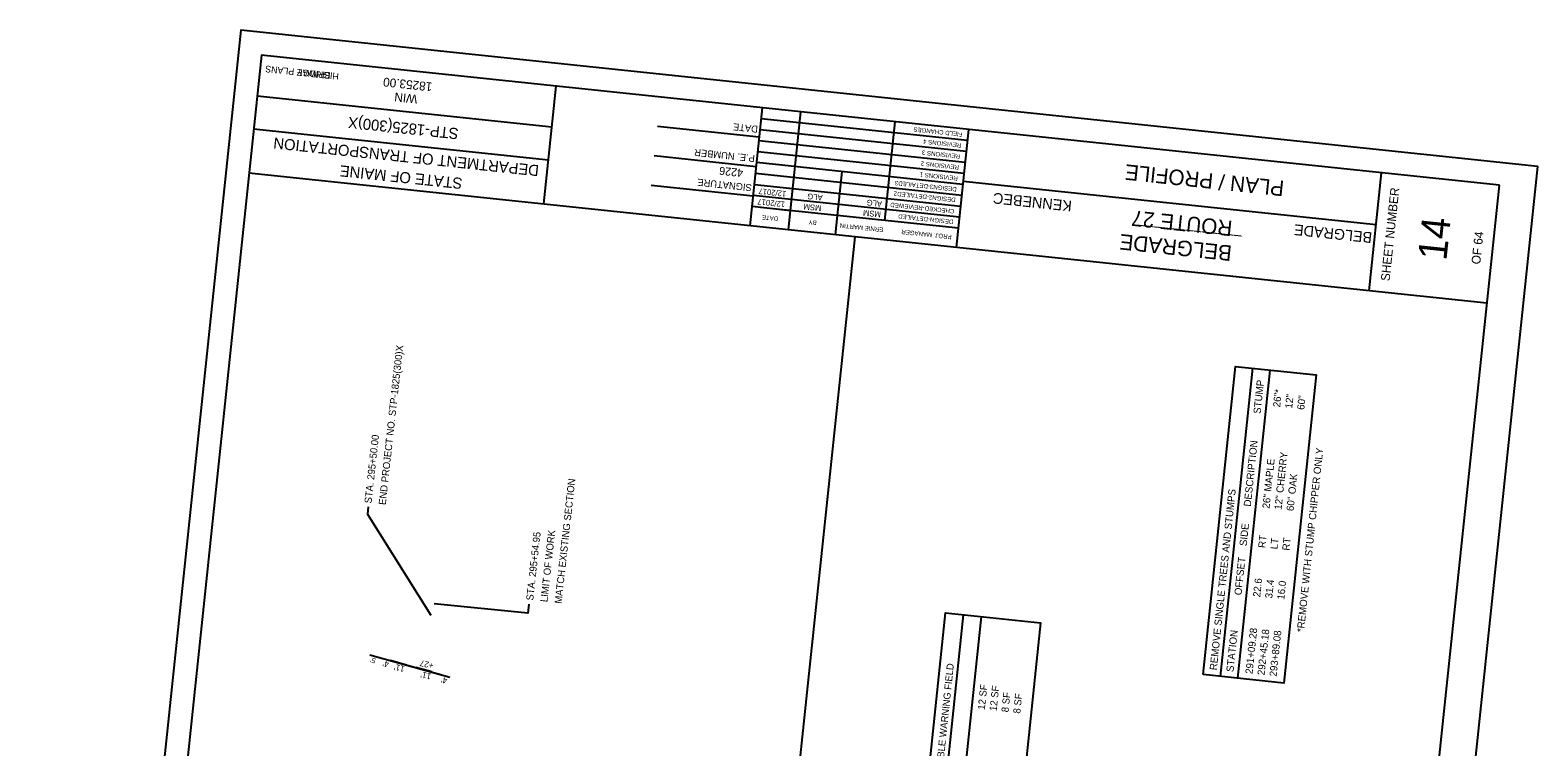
# Model space of a CAD drawing. Extents: x 1111051 to 1111686, y 618367 to 619270.
# Drawn here: x 1111051 to 1111686, y 618968 to 619270 of the extents above; entities that cross this region are included whole.
import ezdxf

# ---------------------------------------------------------------- set-up
doc = ezdxf.new("R2010")
doc.units = 0
for name, color, linetype in [('H_V ANNOTATION', 7, 'Continuous'), ('MINOR', 7, 'Continuous'), ('S_Roadway_Centerline', 7, 'Continuous'), ('S_Roadway_Sidewalks_Paved', 7, 'Continuous'), ('S_Utilities_GuyWire3', 7, 'Continuous')]:
    doc.layers.add(name, color=color, linetype=linetype)

msp = doc.modelspace()

# ---------------------------------------------------------------- linework, layer by layer
at = {"layer": 'MINOR'}
for p, q in [((1111148.14, 619259.69), (1111064.52, 618464.07)), ((1111670.25, 619204.81), (1111148.13, 619259.69)), ((1111267.26, 619196.9), (1111272.48, 619246.62)), ((1111270.65, 619229.34), (1111146.34, 619242.4)), ((1111354.23, 619187.75), (1111359.46, 619237.48)), ((1111269.19, 619215.44), (1111144.88, 619228.5)), ((1111358.15, 619225.05), (1111315.15, 619229.57)), ((1111441.25, 619178.61), (1111446.48, 619228.33)), ((1111356.85, 619212.62), (1111313.85, 619217.14)), ((1111665.02, 619155.09), (1111142.9, 619209.96)), ((1111615.3, 619160.31), (1111620.52, 619210.04)), ((1111355.54, 619200.18), (1111312.54, 619204.7)), ((1111618.22, 619188.12), (1111444.18, 619206.41)), ((1111586.64, 618409.2), (1111670.26, 619204.81)), ((1111320.11, 618437.21), (1111398.5, 619183.1))]:
    msp.add_line(p, q, dxfattribs=at)
for points in [[(1111370.4, 619186.05), (1111375.62, 619235.78)], [(1111445.49, 619219.07), (1111358.49, 619228.22)], [(1111445.98, 619223.71), (1111358.97, 619232.85)], [(1111411.02, 619189.9), (1111415.4, 619231.6)], [(1111445.01, 619214.44), (1111358, 619223.58)], [(1111444.03, 619205.17), (1111357.03, 619214.32)], [(1111444.52, 619209.81), (1111357.51, 619218.95)], [(1111443.55, 619200.54), (1111356.54, 619209.69)], [(1111391.13, 619191.99), (1111393.08, 619210.53)], [(1111356.05, 619205.05), (1111443.06, 619195.91)], [(1111371.24, 619194.08), (1111355.08, 619195.78)], [(1111442.57, 619191.28), (1111355.57, 619200.42)], [(1111442.08, 619186.64), (1111358.59, 619195.42)], [(1111390.29, 619183.96), (1111391.13, 619192)]]:
    msp.add_lwpolyline(points, dxfattribs=at)
at = {"layer": 'S_Roadway_Sidewalks_Paved'}
msp.add_lwpolyline([(1111597.62, 618367.35), (1111686.47, 619212.69), (1111139.49, 619270.18), (1111050.64, 618424.84)], close=True, dxfattribs=at)
at = {"layer": 'S_Utilities_GuyWire3'}
for p, q in [((1111552.66, 618997.7), (1111566.31, 619127.65)), ((1111559.96, 618996.93), (1111573.62, 619126.88)), ((1111433.07, 618917.25), (1111444.25, 619023.7)), ((1111440.6, 618916.46), (1111451.79, 619022.91)), ((1111193.94, 619006.77), (1111227.68, 618997.45)), ((1111209.36, 619002.51), (1111202.62, 619004.37)), ((1111206.47, 619003.31), (1111213.22, 619001.44)), ((1111219.97, 618999.58), (1111213.22, 619001.44)), ((1111217.07, 619000.38), (1111223.82, 618998.51))]:
    msp.add_line(p, q, dxfattribs=at)
for points in [[(1111545.35, 618998.46), (1111559.01, 619128.42), (1111592.98, 619124.85), (1111579.32, 618994.89)], [(1111425.53, 618918.04), (1111436.72, 619024.49), (1111476.79, 619020.28), (1111465.6, 618913.83)]]:
    msp.add_lwpolyline(points, close=True, dxfattribs=at)
for points in [[(1111193.19, 619069.27), (1111192.86, 619066.07), (1111219.58, 619023.54)], [(1111260.99, 619028.14), (1111260.49, 619024.35), (1111220.97, 619028.29)]]:
    msp.add_lwpolyline(points, dxfattribs=at)

# ---------------------------------------------------------------- texts
at = {"layer": 'H_V ANNOTATION'}
for s, height, p in [('BRIDGE PLANS', 2.795, (1111177.42, 619252.38)), ('KENNEBEC', 4.536, (1111490.14, 619198.2)), ('_____________', 4.5358, (1111561.35, 619182.29)), ('BELGRADE', 4.536, (1111616.77, 619184.9))]:
    msp.add_text(s, height=height, rotation=174, dxfattribs=at).set_placement(p)
at = {"layer": 'MINOR'}
for s, height, rotation, p in [('18253.00', 3.726, 174, (1111220.39, 619248.05)), ('WIN', 3.726, 174, (1111214.1, 619242.89)), ('STP-1825(300)X', 4.6588, 174, (1111231.51, 619228.77)), ('DATE', 2.953, 174, (1111357.69, 619229.83)), ('FIELD CHANGES', 1.8637, 174, (1111443.9, 619227.11)), ('DEPARTMENT OF TRANSPORTATION', 4.6588, 174, (1111265.39, 619213.21)), ('REVISIONS 4', 1.8637, 174, (1111443.41, 619222.48)), ('P.E. NUMBER', 2.9528, 174, (1111356.39, 619217.49)), ('REVISIONS 2', 1.8637, 174, (1111442.44, 619213.21)), ('REVISIONS 3', 1.8637, 174, (1111442.93, 619217.84)), ('STATE OF MAINE', 4.6588, 174, (1111233.12, 619207.8)), ('REVISIONS 1', 1.8637, 174, (1111441.95, 619208.58)), ('PLAN / PROFILE', 6.5214, 174, (1111579.74, 619206.61)), ('SIGNATURE', 2.953, 174, (1111355.1, 619205.16)), ('12/2017', 2.423, 174, (1111369.6, 619202.31)), ('DESIGN2-DETAILED2', 1.8637, 174, (1111441, 619199.5)), ('DESIGN3-DETAILED3', 1.8637, 174, (1111441.46, 619203.95)), ('SHEET NUMBER', 3.7264, 84, (1111623.94, 619164.26)), ('12/2017', 2.423, 174, (1111369.13, 619197.87)), ('MSM', 2.423, 174, (1111384.46, 619196.25)), ('ALG', 2.423, 174, (1111384.93, 619200.7)), ('ALG', 2.423, 174, (1111410, 619198.07)), ('CHECKED-REVIEWED', 1.8637, 174, (1111440.49, 619194.68)), ('DATE', 1.857, 174, (1111366.17, 619191.55)), ('BY', 1.857, 174, (1111382.43, 619189.84)), ('MSM', 2.423, 174, (1111409.53, 619193.62)), ('DESIGN-DETAILED', 1.8637, 174, (1111440.02, 619190.23)), ('14', 12.097, 84, (1111647.88, 619172.76)), ('ERNIE MARTIN', 1.8637, 174, (1111410.5, 619186.89)), ('PROJ. MANAGER', 1.8637, 174, (1111439.35, 619183.86)), ('OF 64', 3.726, 84, (1111662.15, 619171.31))]:
    msp.add_text(s, height=height, rotation=rotation, dxfattribs=at).set_placement(p)
at = {"layer": 'S_Roadway_Centerline'}
for s, height, p in [('HIGHWAY PLANS', 2.795, (1111180.94, 619252.01)), ('ROUTE 27', 6.521, (1111557.91, 619189.77)), ('BELGRADE', 6.521, (1111557.69, 619179.3))]:
    msp.add_text(s, height=height, rotation=174, dxfattribs=at).set_placement(p)
at = {"layer": 'S_Utilities_GuyWire3'}
for s, height, rotation, p in [('4226', 3.396, 174, (1111351.46, 619211.57)), ('END PROJECT NO. STP-1825(300)X', 3, 83.68536, (1111200.57, 619069.87)), ('STUMP', 3.066, 84, (1111569.53, 619108.32)), ('26"*', 3.066, 84, (1111577.77, 619111.07)), ('12"', 3.066, 84, (1111582.86, 619110.54)), ('60"', 3.066, 84, (1111587.94, 619110)), ('STA. 295+50.00', 3, 83.68536, (1111194.58, 619070.53)), ('DESCRIPTION', 3.066, 84, (1111565.42, 619069.2)), ('*REMOVE WITH STUMP CHIPPER ONLY', 3.066, 84, (1111587.84, 619016.24)), ('26" MAPLE', 3.066, 84, (1111573.29, 619068.38)), ('12" CHERRY', 3.066, 84, (1111578.37, 619067.84)), ('MATCH EXISTING SECTION', 3, 83.68536, (1111274.74, 619028.25)), ('60" OAK', 3.066, 84, (1111583.45, 619067.31)), ('REMOVE SINGLE TREES AND STUMPS', 3.066, 84, (1111551.07, 619000.2)), ('SIDE', 3.066, 84, (1111563.66, 619052.54)), ('STA. 295+54.95', 3, 83.68536, (1111262.77, 619029.58)), ('LIMIT OF WORK', 3, 83.68536, (1111268.76, 619028.91)), ('RT', 3.066, 84, (1111571.53, 619051.71)), ('LT', 3.066, 84, (1111576.62, 619051.18)), ('RT', 3.066, 84, (1111581.7, 619050.64)), ('OFFSET', 3.066, 84, (1111561.49, 619031.83)), ('22.6', 3.066, 84, (1111569.36, 619031.01)), ('31.4', 3.066, 84, (1111574.44, 619030.47)), ('16.0', 3.066, 84, (1111579.52, 619029.94)), ('291+09.28', 3.066, 84, (1111566.13, 618998.62)), ('292+45.18', 3.066, 84, (1111571.21, 618998.09)), ('STATION', 3.066, 84, (1111558.09, 618999.47)), ('293+89.08', 3.066, 84, (1111576.29, 618997.55)), ("5'", 2.168, 164.25903, (1111196.59, 619005.26)), ('+27', 2.55, 167.22576, (1111220.96, 619003.36)), ("4'", 2.55, 167.22576, (1111202.14, 619003.94)), ("11'", 2.55, 167.22576, (1111208.79, 619002.01)), ("11'", 2.55, 167.22576, (1111219.98, 618998.83)), ('CURB RAMP DETECTABLE WARNING FIELD', 2.9531, 84, (1111431.53, 618920.38)), ("4'", 2.55, 167.22576, (1111226.74, 618997.05)), ('12 SF', 3.006, 84, (1111453.23, 618983.51)), ('12 SF', 3.006, 84, (1111458.21, 618982.99)), ('8 SF', 3.006, 84, (1111463.19, 618982.47)), ('8 SF', 3.006, 84, (1111468.17, 618981.94))]:
    msp.add_text(s, height=height, rotation=rotation, dxfattribs=at).set_placement(p)

doc.saveas('drawing.dxf')
